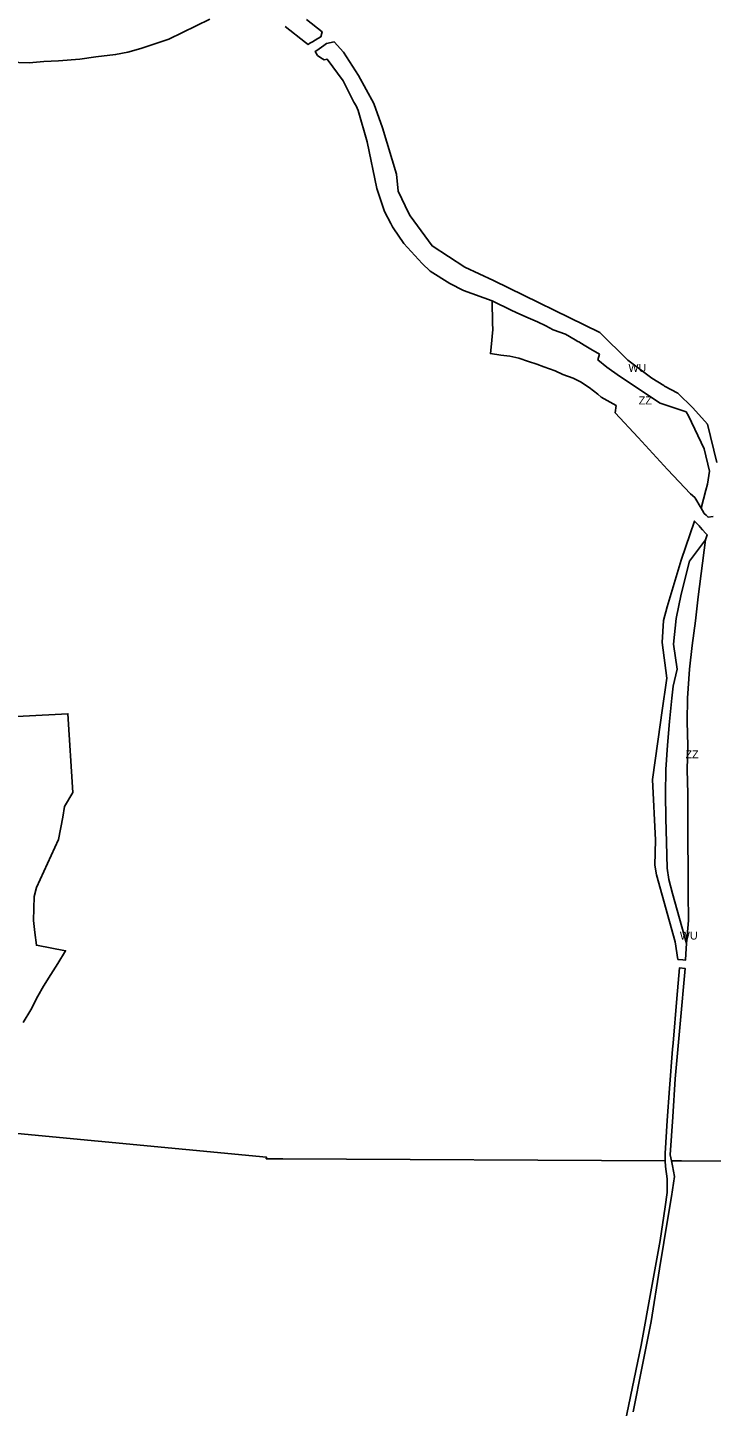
# Model space of a CAD drawing. Extents: x -532067 to -529270, y -1180561 to -1176456.
# Drawn here: x -530711 to -530284, y -1178979 to -1178117 of the extents above; entities that cross this region are included whole.
import ezdxf

# ---------------------------------------------------------------- set-up
doc = ezdxf.new("R2010")
doc.units = 0
for name, color, linetype in [('90630013', 7, 'Continuous'), ('90670013', 7, 'Continuous'), ('90750013', 7, 'Continuous')]:
    doc.layers.add(name, color=color, linetype=linetype)

msp = doc.modelspace()

# ---------------------------------------------------------------- linework, layer by layer
at = {"layer": '90630013'}
for points in [[(-530597.0133, -1178112.12145), (-530622.6703, -1178124.54545), (-530640.0103, -1178130.40245), (-530648.1493, -1178132.70945), (-530655.8443, -1178134.22045), (-530668.1193, -1178135.66845), (-530678.2303, -1178137.10645), (-530691.4163, -1178138.10845), (-530700.6063, -1178138.50845), (-530709.7963, -1178139.31045), (-530729.1753, -1178138.70945)], [(-530536.6333, -1178112.26445), (-530526.6923, -1178120.12245), (-530527.6153, -1178123.06045), (-530529.4133, -1178124.15045), (-530531.0833, -1178125.16245), (-530532.8013, -1178126.20345), (-530534.4113, -1178127.17845), (-530535.5983, -1178127.89845), (-530537.2423, -1178126.59945), (-530549.8433, -1178116.64645)], [(-530282.4863, -1178422.68845), (-530285.6743, -1178423.23545), (-530286.9693, -1178422.02345), (-530288.1853, -1178420.88445), (-530289.2033, -1178419.11145), (-530290.1033, -1178417.54545), (-530286.9863, -1178406.29245), (-530285.9453, -1178402.53445), (-530284.6963, -1178394.39245), (-530288.0263, -1178380.40345), (-530298.0173, -1178359.94245), (-530299.4743, -1178357.43745), (-530315.7093, -1178352.00945), (-530341.1033, -1178335.09745), (-530348.8493, -1178329.41345), (-530354.4693, -1178325.00945), (-530353.5903, -1178321.31045), (-530358.8593, -1178318.31645), (-530363.0733, -1178315.67345), (-530366.4393, -1178313.66845), (-530366.9593, -1178313.35945), (-530368.6933, -1178312.32745), (-530374.8393, -1178308.80445), (-530382.5663, -1178306.16145), (-530386.9563, -1178303.69545), (-530392.2243, -1178301.22945), (-530398.0193, -1178298.76345), (-530403.2883, -1178296.29745), (-530408.2053, -1178294.18345), (-530420.5153, -1178287.96345), (-530438.5163, -1178281.49945), (-530446.9613, -1178277.26345), (-530459.4063, -1178269.46145), (-530464.3113, -1178264.78345), (-530475.7913, -1178252.33945), (-530482.4573, -1178242.49545), (-530482.8273, -1178241.75245), (-530483.9383, -1178239.70945), (-530487.8263, -1178232.28045), (-530492.6403, -1178217.79245), (-530498.7513, -1178188.63345), (-530504.3063, -1178169.13145), (-530505.6023, -1178166.34445), (-530506.8983, -1178163.93045), (-530513.7493, -1178150.55745), (-530523.7483, -1178136.99945), (-530525.5993, -1178137.55645), (-530527.6183, -1178136.17545), (-530529.6733, -1178134.77045), (-530531.1543, -1178132.35645), (-530530.1423, -1178131.64945), (-530528.6113, -1178130.58045), (-530527.2973, -1178129.66245), (-530525.6703, -1178128.52545), (-530523.9963, -1178127.35645), (-530519.2923, -1178126.32345), (-530513.4853, -1178132.75145), (-530504.0723, -1178147.21545), (-530494.4603, -1178164.69145), (-530489.0533, -1178179.95845), (-530480.2413, -1178208.88445), (-530479.2403, -1178219.53145), (-530472.6313, -1178233.59245), (-530471.7843, -1178235.06245), (-530458.1533, -1178253.70745), (-530437.7073, -1178267.06945), (-530419.7383, -1178275.30445), (-530353.4033, -1178307.91445), (-530335.9193, -1178325.05245), (-530320.8863, -1178336.36645), (-530313.2503, -1178341.03145), (-530312.9283, -1178341.27345), (-530304.6783, -1178345.74545), (-530295.3113, -1178354.93245), (-530285.9453, -1178365.16245), (-530280.1173, -1178388.96345)], [(-530337.4573, -1178988.49945), (-530327.5643, -1178940.45745), (-530321.0123, -1178904.84245), (-530315.7153, -1178875.09445), (-530312.4063, -1178854.07645), (-530311.1893, -1178844.99645), (-530311.3183, -1178836.42745), (-530312.3163, -1178828.80845), (-530312.4193, -1178825.19645), (-530312.5503, -1178820.59445), (-530311.2773, -1178800.08645), (-530309.7813, -1178780.10645), (-530307.8353, -1178755.59145), (-530307.5363, -1178751.83145), (-530305.1313, -1178723.79345), (-530303.4863, -1178704.61545), (-530299.9553, -1178705.13045), (-530303.0843, -1178739.61645), (-530306.2123, -1178774.10145), (-530307.7443, -1178797.81445), (-530309.2763, -1178821.52745), (-530308.5643, -1178825.21545), (-530307.9633, -1178828.33445), (-530306.6503, -1178835.14045), (-530308.6203, -1178847.43645), (-530310.5893, -1178859.73145), (-530315.9483, -1178892.63045), (-530321.3073, -1178925.52945), (-530326.8543, -1178953.76245), (-530332.4003, -1178981.99545)]]:
    msp.add_lwpolyline(points, dxfattribs=at)
msp.add_lwpolyline([(-530299.5173, -1178695.94145), (-530299.7663, -1178699.82545), (-530301.3973, -1178699.69445), (-530304.4873, -1178699.44645), (-530306.1493, -1178688.49345), (-530317.9393, -1178646.54845), (-530318.8523, -1178640.65645), (-530318.4513, -1178624.99245), (-530320.4533, -1178587.03845), (-530315.4503, -1178551.35245), (-530314.6023, -1178545.48645), (-530311.4663, -1178523.80445), (-530314.4543, -1178501.39545), (-530313.4583, -1178487.69245), (-530311.2953, -1178479.17245), (-530302.5803, -1178450.14545), (-530294.0883, -1178425.60045), (-530291.3343, -1178428.66945), (-530290.5683, -1178429.52245), (-530289.1763, -1178431.07545), (-530287.0493, -1178433.44545), (-530286.1883, -1178434.20245), (-530287.2483, -1178437.39345), (-530297.2143, -1178450.58045), (-530302.5163, -1178471.21345), (-530305.5833, -1178486.56345), (-530307.2903, -1178502.54445), (-530304.9003, -1178518.06845), (-530307.5173, -1178528.68445), (-530308.4283, -1178536.21845), (-530309.7933, -1178550.82945), (-530311.0453, -1178565.66945), (-530312.0693, -1178580.73645), (-530312.2973, -1178596.14745), (-530312.0693, -1178611.44345), (-530311.7283, -1178626.28245), (-530311.2423, -1178642.40045), (-530310.2983, -1178649.43645), (-530307.8703, -1178658.36745), (-530299.1033, -1178689.48745)], close=True, dxfattribs=at)
at = {"layer": '90670013'}
for points in [[(-530286.9863, -1178406.29245), (-530290.1033, -1178417.54545), (-530293.8783, -1178410.97545), (-530296.7243, -1178408.62345), (-530310.9573, -1178393.50845), (-530329.3753, -1178373.52145), (-530343.6883, -1178357.91645), (-530343.1843, -1178353.47045), (-530352.4813, -1178348.32945), (-530354.6443, -1178346.32345), (-530359.9123, -1178342.27245), (-530365.3563, -1178338.74945), (-530369.9223, -1178336.45945), (-530376.4203, -1178334.16945), (-530381.1613, -1178331.87945), (-530388.3613, -1178329.23745), (-530392.5753, -1178327.65245), (-530397.8443, -1178325.89045), (-530403.8143, -1178323.95245), (-530409.6093, -1178322.54345), (-530415.0533, -1178322.01545), (-530421.6263, -1178320.95545), (-530421.1823, -1178316.94345), (-530420.0753, -1178305.90845), (-530420.2933, -1178302.00745), (-530420.5153, -1178287.96345), (-530408.2053, -1178294.18345), (-530403.2883, -1178296.29745), (-530398.0193, -1178298.76345), (-530392.2243, -1178301.22945), (-530386.9563, -1178303.69545), (-530382.5663, -1178306.16145), (-530374.8393, -1178308.80445), (-530368.6933, -1178312.32745), (-530366.9593, -1178313.35945), (-530366.4393, -1178313.66845), (-530363.0733, -1178315.67345), (-530358.8593, -1178318.31645), (-530353.5903, -1178321.31045), (-530354.4693, -1178325.00945), (-530348.8493, -1178329.41345), (-530341.1033, -1178335.09745), (-530315.7093, -1178352.00945), (-530299.4743, -1178357.43745), (-530298.0173, -1178359.94245), (-530288.0263, -1178380.40345), (-530284.6963, -1178394.39245), (-530285.9453, -1178402.53445)], [(-530297.8893, -1178675.14445), (-530299.1033, -1178689.48745), (-530307.8703, -1178658.36745), (-530310.2983, -1178649.43645), (-530311.2423, -1178642.40045), (-530311.7283, -1178626.28245), (-530312.0693, -1178611.44345), (-530312.2973, -1178596.14745), (-530312.0693, -1178580.73645), (-530311.0453, -1178565.66945), (-530309.7933, -1178550.82945), (-530308.4283, -1178536.21845), (-530307.5173, -1178528.68445), (-530304.9003, -1178518.06845), (-530307.2903, -1178502.54445), (-530305.5833, -1178486.56345), (-530302.5163, -1178471.21345), (-530297.2143, -1178450.58045), (-530287.2483, -1178437.39345), (-530291.9133, -1178472.91445), (-530293.5203, -1178487.93245), (-530295.6823, -1178503.45745), (-530297.3893, -1178518.18245), (-530298.6413, -1178536.33245), (-530298.7553, -1178550.82945), (-530298.3003, -1178566.12545), (-530298.7553, -1178580.85045), (-530298.4143, -1178596.03345), (-530298.4143, -1178611.44345), (-530298.3003, -1178626.16845), (-530298.1583, -1178642.26545), (-530298.0243, -1178658.09645)]]:
    msp.add_lwpolyline(points, close=True, dxfattribs=at)
at = {"layer": '90750013'}
for points in [[(-530741.6833, -1178549.05645), (-530685.6493, -1178546.03445), (-530682.6373, -1178595.14045), (-530687.7583, -1178603.90345), (-530688.8123, -1178610.55145), (-530691.4213, -1178624.48545), (-530705.1493, -1178654.45545), (-530706.7643, -1178660.12545), (-530707.1673, -1178675.11045), (-530706.3603, -1178682.60245), (-530705.2993, -1178690.54345), (-530687.0343, -1178694.01745), (-530691.9913, -1178702.03945), (-530696.3843, -1178708.93245), (-530700.8893, -1178716.05045), (-530704.3813, -1178722.37745), (-530708.8873, -1178730.85145), (-530713.5373, -1178738.81945)], [(-530717.0633, -1178808.11745), (-530561.4833, -1178823.02345), (-530561.6903, -1178823.98545), (-530551.3503, -1178823.99445), (-530312.4193, -1178825.19645), (-530312.3163, -1178828.80845), (-530311.3183, -1178836.42745), (-530311.1893, -1178844.99645), (-530312.4063, -1178854.07645), (-530315.7153, -1178875.09445), (-530321.0123, -1178904.84245), (-530327.5643, -1178940.45745), (-530337.4573, -1178988.49945)], [(-530332.4003, -1178981.99545), (-530326.8543, -1178953.76245), (-530321.3073, -1178925.52945), (-530315.9483, -1178892.63045), (-530310.5893, -1178859.73145), (-530308.6203, -1178847.43645), (-530306.6503, -1178835.14045), (-530307.9633, -1178828.33445), (-530308.5643, -1178825.21545), (-530302.3453, -1178825.24745), (-530236.1433, -1178825.58045)]]:
    msp.add_lwpolyline(points, dxfattribs=at)

# ---------------------------------------------------------------- texts
at = {"layer": '90630013'}
for rotation, p in [(0.00000003, (-530335.44176, -1178332.41945)), (359.99999993, (-530303.3208, -1178687.02838))]:
    msp.add_text('WU', height=5, rotation=rotation, dxfattribs=at).set_placement(p)
at = {"layer": '90670013'}
for rotation, p in [(0.00000002, (-530328.98007, -1178352.75445)), (0.00000003, (-530299.7728, -1178573.82396))]:
    msp.add_text('ZZ', height=5, rotation=rotation, dxfattribs=at).set_placement(p)

doc.saveas('drawing.dxf')
